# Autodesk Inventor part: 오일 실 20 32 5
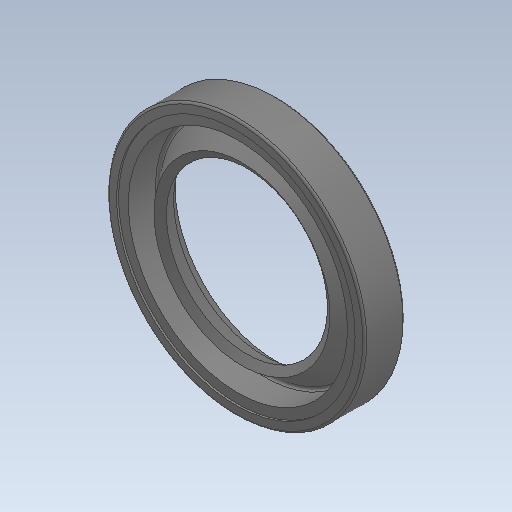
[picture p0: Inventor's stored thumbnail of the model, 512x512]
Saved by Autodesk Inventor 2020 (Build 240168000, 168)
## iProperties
Created: 2024-04
Part Number: 오일 실 20 32 5
Material: 고무
Description: 오일 실 - 비스프링, 조립 GA
Document SubType Name: Modeling
Designer: oem
Density: 0.93 g/cm^3
Appearance: 기본값
Mass: 1.40735 g
Surface Area: 20.5861 cm^2
Volume: 1.51328 cm^3
Sending System: Autodesk Inventor 2025
Preprocessor: ST-DEVELOPER v20
Author: jhkim
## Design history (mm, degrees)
feature "Solid1"
node "솔리드1"
